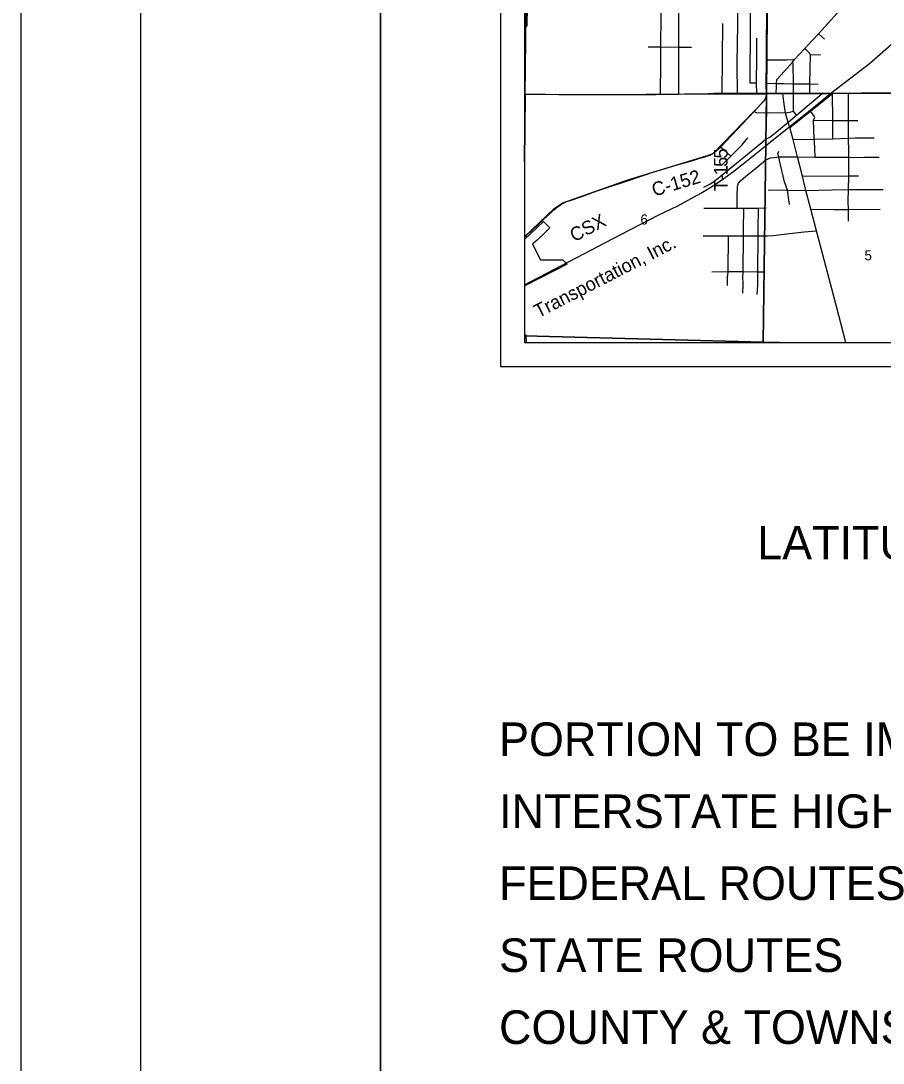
# Model space of a CAD drawing. Extents: x 0 to 34, y 0 to 22.
# Drawn here: x 0 to 3.596, y 11.095 to 15.439 of the extents above; entities that cross this region are included whole.
import ezdxf

# ---------------------------------------------------------------- set-up
doc = ezdxf.new("R2010")
doc.units = 0
for name, color, linetype in [('GM_X_City_Street', 7, 'Continuous'), ('GM_X_Corporation', 7, 'Continuous'), ('GM_X_County_Road', 7, 'Continuous'), ('GM_X_County_Road_Text', 7, 'Continuous'), ('GM_X_Rail_Line', 7, 'Continuous'), ('GM_X_Rail_Line_Text', 7, 'Continuous'), ('GM_X_Section_Text', 7, 'Continuous'), ('GM_X_State_Route', 7, 'Continuous'), ('GM_X_Township_Road_Text', 7, 'Continuous'), ('SH_Border', 7, 'Continuous'), ('SH_Cut_Line', 7, 'Continuous'), ('SH_Data', 7, 'Continuous'), ('SH_Text', 7, 'Continuous')]:
    doc.layers.add(name, color=color, linetype=linetype)

msp = doc.modelspace()

# ---------------------------------------------------------------- linework, layer by layer
at = {"layer": 'GM_X_City_Street'}
for p, q in [((2.9254, 15.1385), (2.9271, 15.4272)), ((3.3271, 15.3851), (3.3515, 15.3622)), ((3.2926, 15.2987), (3.3355, 15.2972))]:
    msp.add_line(p, q, dxfattribs=at)
for points in [[(2.6675, 15.1326), (2.6692, 15.2644), (2.6684, 15.3298), (2.6702, 15.4583), (2.6708, 15.505), (2.6696, 15.619), (2.6704, 15.6647), (2.6727, 15.7883), (2.6734, 15.8265)], [(2.7438, 15.1333), (2.7445, 15.1633), (2.7438, 15.2749), (2.7436, 15.3289), (2.7435, 15.5056), (2.7435, 15.633), (2.7435, 15.6494), (2.7406, 15.6626), (2.7396, 15.6671), (2.7337, 15.6987), (2.7352, 15.7871), (2.7357, 15.8167)], [(3.0429, 15.4242), (3.0448, 15.555), (3.0461, 15.6428)], [(2.9879, 15.2619), (2.9899, 15.4219), (2.9882, 15.5544), (2.9887, 15.5811)], [(3.1506, 15.1361), (3.1512, 15.1639), (3.151, 15.1716), (3.1508, 15.1776), (3.1523, 15.1947), (3.1845, 15.2291), (3.2195, 15.2674), (3.2265, 15.2771), (3.2679, 15.3215), (3.281, 15.3362), (3.3271, 15.3851), (3.4048, 15.4712), (3.4239, 15.4916), (3.4385, 15.5071)], [(3.068, 15.1789), (3.0417, 15.1789), (3.0428, 15.4159), (3.0429, 15.4242)], [(3.0696, 15.1376), (3.068, 15.1789), (3.069, 15.2887), (3.0691, 15.3663)], [(2.6161, 15.3303), (2.6667, 15.3298), (2.6684, 15.3298), (2.7436, 15.3289), (2.7972, 15.3283)], [(3.2905, 15.1687), (3.2905, 15.1698), (3.2906, 15.1764), (3.2926, 15.2987), (3.2885, 15.3038), (3.2758, 15.3165), (3.2679, 15.3215)], [(2.9888, 15.1378), (2.9879, 15.2557), (2.9879, 15.2619)], [(3.1101, 15.2766), (3.1371, 15.276), (3.193, 15.2766), (3.2265, 15.2771)], [(3.2225, 15.1369), (3.2222, 15.1683), (3.2221, 15.1762), (3.2213, 15.2598), (3.2195, 15.2674)], [(3.108, 15.1784), (3.1508, 15.1776), (3.181, 15.1775), (3.2221, 15.1762), (3.2906, 15.1764), (3.3067, 15.1754), (3.3249, 15.1758)], [(3.2904, 15.1359), (3.2904, 15.1624), (3.2905, 15.1687)], [(2.8487, 14.7455), (2.876, 14.7599), (2.9016, 14.7775), (3.1057, 14.9444), (3.1236, 14.9537), (3.143, 14.969), (3.1761, 14.9972), (3.1999, 15.0167), (3.2347, 15.046), (3.3425, 15.1352)], [(3.2068, 14.9935), (3.293, 15.0616), (3.3851, 15.1361)], [(3.2347, 15.046), (3.2218, 15.0626), (3.2225, 15.1369)], [(3.3866, 14.9469), (3.3859, 15.0237), (3.3851, 15.1361)], [(3.4509, 14.6859), (3.4509, 14.6869), (3.4517, 14.7354), (3.4528, 14.793), (3.4527, 14.8701), (3.4531, 14.9039), (3.4519, 14.9388), (3.4519, 14.95), (3.4519, 15.023), (3.4519, 15.0892), (3.4517, 15.1368)], [(3.1104, 15.0449), (3.1107, 15.0558), (3.111, 15.1087)], [(3.0577, 15.0608), (3.0666, 15.0567), (3.1107, 15.0558), (3.1213, 15.0561), (3.1894, 15.0557), (3.2059, 15.0578), (3.2218, 15.0626)], [(3.1057, 14.9444), (3.1085, 14.9647), (3.1095, 15.0139), (3.11, 15.0322), (3.1104, 15.0449)], [(3.3126, 14.8707), (3.3094, 14.9387), (3.3091, 14.9459), (3.3054, 15.0248), (3.3119, 15.0356), (3.306, 15.0452), (3.293, 15.0616)], [(3.3054, 15.0248), (3.3859, 15.0237), (3.4519, 15.023), (3.4909, 15.023)], [(2.9218, 14.836), (2.9612, 14.8752), (2.9825, 14.8969), (3.0063, 14.9207), (3.0319, 14.9506)], [(3.2203, 14.944), (3.3091, 14.9459), (3.3866, 14.9469), (3.4519, 14.95), (3.4788, 14.9511), (3.5586, 14.9514)], [(2.9612, 14.8752), (2.9314, 14.9015), (2.918, 14.9128)], [(2.9869, 14.6573), (2.9873, 14.7073), (2.9881, 14.7491), (2.9924, 14.7616), (3.0019, 14.7723), (3.0239, 14.7912), (3.0566, 14.8175), (3.107, 14.8588), (3.1265, 14.8681), (3.1412, 14.8698), (3.1606, 14.8723), (3.2386, 14.8716)], [(3.2058, 14.6738), (3.1969, 14.7328), (3.1853, 14.7682), (3.1644, 14.8561), (3.1606, 14.8723), (3.157, 14.8863), (3.1617, 14.8958)], [(3.2386, 14.8716), (3.3126, 14.8707), (3.4527, 14.8701), (3.4686, 14.8696), (3.5165, 14.8711), (3.5789, 14.8711)], [(3.2592, 14.7915), (3.4528, 14.793), (3.4615, 14.7927), (3.4937, 14.7926)], [(3.1162, 14.7339), (3.1969, 14.7328), (3.274, 14.7321)], [(3.274, 14.7321), (3.3841, 14.7341), (3.4517, 14.7354), (3.5959, 14.7355)], [(3.4519, 14.6044), (3.4514, 14.6416), (3.4515, 14.6529), (3.4509, 14.6859)], [(2.8488, 14.6583), (2.9869, 14.6573), (3.0157, 14.6578), (3.0762, 14.6582), (3.1086, 14.6588)], [(3.0117, 14.3852), (3.0118, 14.3946), (3.0141, 14.5421), (3.0135, 14.5643), (3.0157, 14.6578)], [(3.0736, 14.3806), (3.0738, 14.3932), (3.0749, 14.5423), (3.0754, 14.5666), (3.0762, 14.6582)], [(3.2941, 14.6535), (3.39, 14.6527), (3.4515, 14.6529), (3.584, 14.6534)], [(3.1139, 14.5433), (3.1377, 14.5445), (3.2051, 14.553), (3.267, 14.5596), (3.3185, 14.5639)], [(2.8462, 14.543), (2.9111, 14.5431), (2.9511, 14.5421), (3.0141, 14.5421), (3.0749, 14.5423), (3.0912, 14.5423), (3.1129, 14.5432), (3.1139, 14.5433)], [(2.9479, 14.3775), (2.9502, 14.3938), (2.9511, 14.5421)], [(2.8811, 14.3931), (2.9502, 14.3938), (3.0118, 14.3946), (3.0738, 14.3932), (3.1036, 14.393)], [(3.011, 14.3043), (3.0119, 14.3419), (3.0115, 14.3748), (3.0117, 14.3852)], [(3.0709, 14.2986), (3.074, 14.3371), (3.0735, 14.3754), (3.0736, 14.3806)], [(2.9474, 14.3358), (2.9476, 14.3755), (2.9479, 14.3775)]]:
    msp.add_lwpolyline(points, dxfattribs=at)
at = {"layer": 'GM_X_Corporation'}
for points in [[(2.1, 20.898), (2.1, 14.098), (8.9, 14.098), (8.9, 19.3874)], [(3.8843, 15.1371), (3.1092, 15.1326), (3.1186, 16.1305)], [(2.1127, 15.5867), (2.1107, 15.417), (2.1, 15.4171), (2.1, 14.528), (2.1791, 14.6027), (2.2059, 14.5757), (2.1894, 14.56), (2.164, 14.5358), (2.1543, 14.5265), (2.1341, 14.5073), (2.1674, 14.443), (2.26, 14.4431), (2.2782, 14.4252), (2.1017, 14.3345), (2.1, 14.3336), (2.1, 14.1305), (2.1065, 14.1305), (2.1072, 14.098), (3.6049, 14.098)], [(3.8843, 15.1371), (3.1092, 15.1326), (3.0953, 14.1), (3.164, 14.098), (4.1253, 14.098)]]:
    msp.add_lwpolyline(points, dxfattribs=at)
for points in [[(2.1, 16.1403), (2.1, 15.1304), (2.1027, 15.1304), (2.1158, 16.1403)], [(2.1158, 16.1403), (3.1186, 16.1305), (3.1092, 15.1326), (2.1027, 15.1304)], [(2.1, 14.8511), (2.1, 14.1262), (3.0953, 14.1), (3.1092, 15.1326), (2.1027, 15.1304)], [(2.1, 15.1304), (2.1, 14.8511), (2.1027, 15.1304)], [(2.1, 14.1262), (2.1, 14.098), (3.0953, 14.098), (3.0953, 14.1)], [(3.0953, 14.098), (3.164, 14.098), (3.0953, 14.1)]]:
    msp.add_lwpolyline(points, close=True, dxfattribs=at)
at = {"layer": 'GM_X_County_Road'}
for points in [[(3.1093, 15.1371), (3.1078, 15.1674), (3.108, 15.1784), (3.11, 15.2674), (3.1101, 15.2766), (3.1116, 15.5332), (3.1118, 15.5552)], [(2.8483, 14.87), (2.8737, 14.8792), (2.892, 14.8897), (2.918, 14.9128), (2.9401, 14.9359), (3.0577, 15.0608), (3.084, 15.0902), (3.1066, 15.1151), (3.1092, 15.1222), (3.1093, 15.1371)], [(3.4401, 14.098), (3.4022, 14.2475), (3.3185, 14.5639), (3.2941, 14.6535), (3.274, 14.7321), (3.2592, 14.7915), (3.2386, 14.8716), (3.2203, 14.944), (3.2068, 14.9935), (3.1999, 15.0167), (3.1948, 15.0338), (3.1894, 15.0557), (3.1827, 15.0911), (3.1778, 15.1357)], [(2.6114, 14.7995), (2.6235, 14.8035), (2.7371, 14.838), (2.7979, 14.8555), (2.8315, 14.8657), (2.8483, 14.87)], [(2.1, 14.5369), (2.1068, 14.5431), (2.1342, 14.5683), (2.2208, 14.6495), (2.2323, 14.6591), (2.2499, 14.6718), (2.2734, 14.6838), (2.2906, 14.6899), (2.3389, 14.7069), (2.4032, 14.7298), (2.4571, 14.7478), (2.5048, 14.7642), (2.6114, 14.7995)]]:
    msp.add_lwpolyline(points, dxfattribs=at)
at = {"layer": 'GM_X_Rail_Line'}
for points in [[(3.3781, 15.1371), (3.7625, 15.1411), (3.8908, 15.1437), (4.1071, 15.2029), (4.1979, 15.1964), (4.4021, 15.1525), (4.503, 15.1372), (4.7705, 15.1123), (4.89, 15.0915), (4.9836, 15.0897), (5.1669, 15.0922), (5.1739, 15.0968), (5.1979, 15.3351), (5.2386, 15.6999)], [(2.1, 14.3391), (2.5015, 14.5477), (2.6602, 14.6297), (2.7404, 14.6679), (2.8356, 14.7212), (2.8845, 14.7498), (2.9315, 14.7815), (2.9735, 14.8123), (3.0395, 14.8654), (3.1402, 14.9454), (3.2994, 15.0726), (3.3783, 15.1366), (3.5398, 15.2612), (3.6524, 15.359), (3.745, 15.434), (3.8337, 15.5051)], [(2.1, 14.5387), (2.2247, 14.6566), (2.2604, 14.6803), (2.5319, 14.7756), (2.8864, 14.8846), (3.1006, 15.1049), (3.1088, 15.1209), (3.1095, 15.1326), (3.1197, 15.1378), (3.3781, 15.1371)]]:
    msp.add_lwpolyline(points, dxfattribs=at)
at = {"layer": 'GM_X_State_Route'}
msp.add_line((2.1, 15.1336), (2.1031, 15.1337), dxfattribs=at)
for points in [[(2.1031, 15.1337), (2.1582, 15.1329), (2.188, 15.1333), (2.2438, 15.1323), (2.2814, 15.132), (2.2834, 15.132)], [(2.2834, 15.132), (2.3057, 15.132), (2.3714, 15.1319), (2.404, 15.1319)], [(2.404, 15.1319), (2.4356, 15.1318), (2.4925, 15.1319), (2.5043, 15.1318)], [(2.5043, 15.1318), (2.5199, 15.1317), (2.5511, 15.1314), (2.5809, 15.1317), (2.6092, 15.1317), (2.628, 15.1318), (2.6486, 15.1315), (2.6675, 15.1326), (2.6746, 15.1327)], [(2.6746, 15.1327), (2.692, 15.1329), (2.7215, 15.1332), (2.7438, 15.1333), (2.7682, 15.1339), (2.8117, 15.1341), (2.8665, 15.1358), (2.8907, 15.1372), (2.9254, 15.1385)], [(2.9254, 15.1385), (2.9541, 15.1376), (2.9888, 15.1378), (3.042, 15.1373), (3.0696, 15.1376), (3.1093, 15.1371), (3.1189, 15.1366)], [(3.1189, 15.1366), (3.1275, 15.1362), (3.1506, 15.1361), (3.1778, 15.1357)], [(3.1778, 15.1357), (3.1999, 15.1368), (3.2225, 15.1369), (3.2557, 15.1364), (3.2904, 15.1359), (3.3188, 15.1357), (3.3425, 15.1352), (3.3831, 15.136)], [(3.3831, 15.136), (3.3851, 15.1361), (3.419, 15.1367), (3.4517, 15.1368), (3.479, 15.1367), (3.506, 15.1372), (3.5431, 15.137), (3.5595, 15.1374)], [(3.5595, 15.1374), (3.5614, 15.1375), (3.6028, 15.1388), (3.627, 15.1391), (3.6527, 15.1388), (3.6938, 15.1382), (3.733, 15.1378), (3.7543, 15.1377), (3.7553, 15.1377)]]:
    msp.add_lwpolyline(points, dxfattribs=at)
at = {"layer": 'SH_Border'}
for points in [[(0.5, 21.498), (1.5, 21.498), (1.5, 0.498), (0.5, 0.498)], [(1.5, 21.498), (33.5, 21.498), (33.5, 0.498), (1.5, 0.498)]]:
    msp.add_lwpolyline(points, close=True, dxfattribs=at)
at = {"layer": 'SH_Cut_Line'}
msp.add_lwpolyline([(0, -0.002), (34, -0.002), (34, 21.998), (0, 21.998)], close=True, dxfattribs=at)
at = {"layer": 'SH_Data'}
for p, q in [((2, 20.998), (2, 13.998)), ((2.1, 20.898), (2.1, 14.098)), ((2.1, 14.098), (8.9, 14.098)), ((2.1, 14.098), (2.1, 14.098)), ((2, 13.998), (9, 13.998))]:
    msp.add_line(p, q, dxfattribs=at)

# ---------------------------------------------------------------- texts
at = {"layer": 'GM_X_County_Road_Text'}
msp.add_text('C-152', height=0.05682, rotation=16.6211, dxfattribs=at).set_placement((2.6412, 14.7062))
at = {"layer": 'GM_X_Rail_Line_Text'}
for s, height, rotation, p in [('CSX', 0.05663, 27.5126, (2.3079, 14.5156)), ('Transportation, Inc.', 0.056629, 27.1442, (2.1583, 14.1992))]:
    msp.add_text(s, height=height, rotation=rotation, dxfattribs=at).set_placement(p)
at = {"layer": 'GM_X_Section_Text'}
for s, p in [('6', (2.584, 14.5899)), ('5', (3.5181, 14.4405))]:
    msp.add_text(s, height=0.0419, rotation=0, dxfattribs=at).set_placement(p)
at = {"layer": 'GM_X_Township_Road_Text'}
for s, rotation, p in [('5', 90.0026, (2.9472, 14.865)), ('5', 90.0078, (2.9472, 14.83)), ('1', 90.0625, (2.9472, 14.7951)), ('T', 90.8593, (2.9479, 14.7294)), ('-', 90.1952, (2.9473, 14.7718))]:
    msp.add_text(s, height=0.0568, rotation=rotation, dxfattribs=at).set_placement(p)
at = {"layer": 'SH_Text'}
for s, p in [('LATITUDE:  39.516823    LONGITUDE:  -84.410204', (3.071, 13.1939)), ('PORTION TO BE IMPROVED', (1.9944, 12.3747)), ('INTERSTATE HIGHWAY', (1.9944, 12.0747)), ('FEDERAL ROUTES', (1.9944, 11.7747)), ('STATE ROUTES', (1.9944, 11.4747)), ('COUNTY & TOWNSHIP ROADS', (1.9944, 11.1747))]:
    msp.add_text(s, height=0.14, dxfattribs=at).set_placement(p)

doc.saveas('drawing.dxf')
